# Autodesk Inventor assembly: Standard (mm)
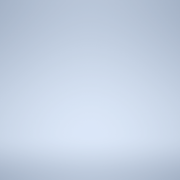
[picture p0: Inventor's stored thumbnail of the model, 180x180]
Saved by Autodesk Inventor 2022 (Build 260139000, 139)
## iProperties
Created: 2021-02
Part Number: Standard (mm)
Document SubType Name: Assembly
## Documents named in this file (1)
- C:\Users\ENU\Desktop\New folder for ita\Standard (mm).iam
